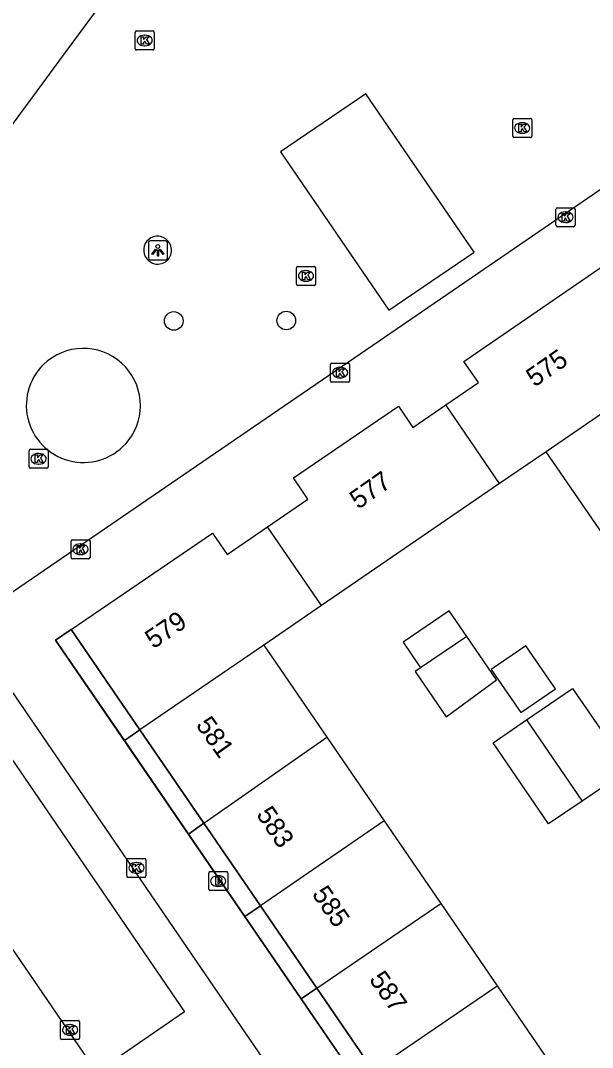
# Model space of a CAD drawing. Extents: x 155275 to 156263, y 382654 to 383635.
# Drawn here: x 155775.3 to 155805.4, y 383214.4 to 383268.4 of the extents above; entities that cross this region are included whole.
import ezdxf

# ---------------------------------------------------------------- set-up
doc = ezdxf.new("R2010")
doc.units = 0
for name, color, linetype in [('IMGEO_Boom', 7, 'Continuous'), ('IMGEO_Brandkraan', 7, 'Continuous'), ('IMGEO_Kolk', 7, 'Continuous'), ('IMGEO_Lichtpunt', 7, 'Continuous'), ('IMGEO_Pand', 7, 'Continuous'), ('IMGEO_Pand_nummerreeks', 7, 'Continuous'), ('IMGEO_Pand_overbouw', 7, 'Continuous'), ('IMGEO_Rijbaan_lokaal_open', 7, 'Continuous'), ('IMGEO_Voetpad_open', 7, 'Continuous')]:
    doc.layers.add(name, color=color, linetype=linetype)

msp = doc.modelspace()

# ---------------------------------------------------------------- linework, layer by layer
at = {"layer": 'IMGEO_Boom'}
for centre in [(155789.292, 383252.661), (155783.378, 383252.641)]:
    msp.add_circle(centre, 0.489, dxfattribs=at)
at = {"layer": 'IMGEO_Brandkraan'}
for p, q in [((155785.216, 383222.754), (155785.216, 383223.606)), ((155785.291, 383223.68), (155786.143, 383223.68)), ((155785.704, 383223.46), (155785.729, 383223.46)), ((155786.217, 383223.606), (155786.217, 383222.754)), ((155785.727, 383222.9), (155785.702, 383222.9)), ((155786.143, 383222.68), (155785.291, 383222.68))]:
    msp.add_line(p, q, dxfattribs=at)
for points in [[(155785.216, 383222.754), (155785.216, 383223.606)], [(155785.291, 383223.68), (155786.143, 383223.68)], [(155786.217, 383223.606), (155786.217, 383222.754)], [(155785.564, 383223.38), (155785.564, 383222.98), (155785.777, 383222.98)], [(155785.795, 383223.38), (155785.564, 383223.38)], [(155785.743, 383223.299), (155785.689, 383223.299), (155785.689, 383223.223)], [(155785.689, 383223.223), (155785.742, 383223.223)], [(155785.751, 383223.147), (155785.689, 383223.147), (155785.689, 383223.066)], [(155785.689, 383223.066), (155785.751, 383223.066)], [(155786.143, 383222.68), (155785.291, 383222.68)]]:
    msp.add_lwpolyline(points, dxfattribs=at)
for centre, radius, start, end in [((155785.293, 383223.604), 0.0765, 91.552, 178.448), ((155785.293, 383223.604), 0.0765, 91.552, 178.448), ((155786.141, 383223.604), 0.0765, 1.552, 88.448), ((155786.141, 383223.604), 0.0765, 1.552, 88.448), ((155785.744, 383223.261), 0.0379, 267.8285, 90.9355), ((155785.752, 383223.106), 0.0404, 269.8759, 90.5077), ((155785.783, 383223.231), 0.251, 268.6676, 293.5347), ((155785.799, 383223.235), 0.145, 59.4692, 91.5367), ((155785.824, 383223.282), 0.0922, 285.5137, 58.1501), ((155785.829, 383223.09), 0.105, 301.3115, 78.989), ((155785.293, 383222.756), 0.0765, 181.552, 268.448), ((155785.293, 383222.756), 0.0765, 181.552, 268.448), ((155786.141, 383222.756), 0.0765, 271.552, 358.448), ((155786.141, 383222.756), 0.0765, 271.552, 358.448)]:
    msp.add_arc(centre, radius, start, end, dxfattribs=at)
for centre, major_axis, ratio, start_param, end_param in [((155785.703, 383223.18), (-0.387, 0.002), 0.722429, 4.712389, 7.853982), ((155785.728, 383223.18), (-0.39, 0.002), 0.717154, 1.570796, 4.712389)]:
    msp.add_ellipse(centre, major_axis=major_axis, ratio=ratio, start_param=start_param, end_param=end_param, dxfattribs=at)
at = {"layer": 'IMGEO_Kolk'}
for p, q in [((155781.349, 383266.964), (155781.349, 383267.816)), ((155781.424, 383267.89), (155782.276, 383267.89)), ((155782.35, 383267.816), (155782.35, 383266.964)), ((155781.837, 383267.67), (155781.862, 383267.67)), ((155782.276, 383266.89), (155781.424, 383266.89)), ((155781.86, 383267.11), (155781.835, 383267.11)), ((155801.197, 383262.362), (155801.197, 383263.214)), ((155801.272, 383263.288), (155802.124, 383263.288)), ((155801.685, 383263.068), (155801.71, 383263.068)), ((155802.198, 383263.214), (155802.198, 383262.362)), ((155801.708, 383262.508), (155801.683, 383262.508)), ((155802.124, 383262.288), (155801.272, 383262.288)), ((155803.546, 383258.596), (155804.398, 383258.596)), ((155803.471, 383257.67), (155803.471, 383258.522)), ((155803.959, 383258.376), (155803.984, 383258.376)), ((155804.472, 383258.522), (155804.472, 383257.67)), ((155804.398, 383257.596), (155803.546, 383257.596)), ((155803.982, 383257.816), (155803.957, 383257.816)), ((155789.828, 383254.582), (155789.828, 383255.434)), ((155789.903, 383255.508), (155790.755, 383255.508)), ((155790.829, 383255.434), (155790.829, 383254.582)), ((155790.316, 383255.288), (155790.341, 383255.288)), ((155790.755, 383254.508), (155789.903, 383254.508)), ((155790.339, 383254.728), (155790.314, 383254.728)), ((155791.619, 383249.496), (155791.619, 383250.348)), ((155791.694, 383250.422), (155792.546, 383250.422)), ((155792.107, 383250.202), (155792.132, 383250.202)), ((155792.62, 383250.348), (155792.62, 383249.496)), ((155792.546, 383249.422), (155791.694, 383249.422)), ((155792.13, 383249.642), (155792.105, 383249.642)), ((155775.773, 383244.964), (155775.773, 383245.816)), ((155775.848, 383245.89), (155776.7, 383245.89)), ((155776.261, 383245.67), (155776.286, 383245.67)), ((155776.774, 383245.816), (155776.774, 383244.964)), ((155776.284, 383245.11), (155776.259, 383245.11)), ((155776.7, 383244.89), (155775.848, 383244.89)), ((155777.978, 383240.206), (155777.978, 383241.058)), ((155778.053, 383241.132), (155778.905, 383241.132)), ((155778.466, 383240.912), (155778.491, 383240.912)), ((155778.979, 383241.058), (155778.979, 383240.206)), ((155778.489, 383240.352), (155778.464, 383240.352)), ((155778.905, 383240.132), (155778.053, 383240.132)), ((155780.913, 383223.451), (155780.913, 383224.303)), ((155780.988, 383224.377), (155781.84, 383224.377)), ((155781.401, 383224.157), (155781.426, 383224.157)), ((155781.914, 383224.303), (155781.914, 383223.451)), ((155781.424, 383223.597), (155781.399, 383223.597)), ((155781.84, 383223.377), (155780.988, 383223.377)), ((155777.425, 383214.927), (155777.425, 383215.779)), ((155777.5, 383215.853), (155778.352, 383215.853)), ((155777.913, 383215.633), (155777.938, 383215.633)), ((155778.426, 383215.779), (155778.426, 383214.927)), ((155778.352, 383214.853), (155777.5, 383214.853)), ((155777.936, 383215.073), (155777.911, 383215.073))]:
    msp.add_line(p, q, dxfattribs=at)
for points in [[(155781.349, 383266.964), (155781.349, 383267.816)], [(155781.424, 383267.89), (155782.276, 383267.89)], [(155782.35, 383267.816), (155782.35, 383266.964)], [(155781.67, 383267.59), (155781.793, 383267.59), (155781.793, 383267.439), (155781.923, 383267.59), (155782.087, 383267.59), (155781.941, 383267.439), (155782.094, 383267.19), (155781.942, 383267.19), (155781.857, 383267.354), (155781.793, 383267.287), (155781.793, 383267.19), (155781.67, 383267.19), (155781.67, 383267.59)], [(155782.276, 383266.89), (155781.424, 383266.89)], [(155801.197, 383262.362), (155801.197, 383263.214)], [(155801.272, 383263.288), (155802.124, 383263.288)], [(155801.518, 383262.988), (155801.641, 383262.988), (155801.641, 383262.837), (155801.771, 383262.988), (155801.935, 383262.988), (155801.789, 383262.837), (155801.942, 383262.588), (155801.79, 383262.588), (155801.705, 383262.752), (155801.641, 383262.685), (155801.641, 383262.588), (155801.518, 383262.588), (155801.518, 383262.988)], [(155802.198, 383263.214), (155802.198, 383262.362)], [(155802.124, 383262.288), (155801.272, 383262.288)], [(155803.546, 383258.596), (155804.398, 383258.596)], [(155803.471, 383257.67), (155803.471, 383258.522)], [(155803.792, 383258.296), (155803.915, 383258.296), (155803.915, 383258.145), (155804.045, 383258.296), (155804.209, 383258.296), (155804.063, 383258.145), (155804.216, 383257.896), (155804.064, 383257.896), (155803.979, 383258.06), (155803.915, 383257.993), (155803.915, 383257.896), (155803.792, 383257.896), (155803.792, 383258.296)], [(155804.472, 383258.522), (155804.472, 383257.67)], [(155804.398, 383257.596), (155803.546, 383257.596)], [(155789.828, 383254.582), (155789.828, 383255.434)], [(155789.903, 383255.508), (155790.755, 383255.508)], [(155790.829, 383255.434), (155790.829, 383254.582)], [(155790.149, 383255.208), (155790.272, 383255.208), (155790.272, 383255.057), (155790.402, 383255.208), (155790.566, 383255.208), (155790.42, 383255.057), (155790.573, 383254.808), (155790.421, 383254.808), (155790.336, 383254.972), (155790.272, 383254.905), (155790.272, 383254.808), (155790.149, 383254.808), (155790.149, 383255.208)], [(155790.755, 383254.508), (155789.903, 383254.508)], [(155791.619, 383249.496), (155791.619, 383250.348)], [(155791.694, 383250.422), (155792.546, 383250.422)], [(155791.94, 383250.122), (155792.063, 383250.122), (155792.063, 383249.971), (155792.193, 383250.122), (155792.357, 383250.122), (155792.211, 383249.971), (155792.364, 383249.722), (155792.212, 383249.722), (155792.127, 383249.886), (155792.063, 383249.819), (155792.063, 383249.722), (155791.94, 383249.722), (155791.94, 383250.122)], [(155792.62, 383250.348), (155792.62, 383249.496)], [(155792.546, 383249.422), (155791.694, 383249.422)], [(155775.773, 383244.964), (155775.773, 383245.816)], [(155775.848, 383245.89), (155776.7, 383245.89)], [(155776.094, 383245.59), (155776.217, 383245.59), (155776.217, 383245.439), (155776.347, 383245.59), (155776.511, 383245.59), (155776.365, 383245.439), (155776.518, 383245.19), (155776.366, 383245.19), (155776.281, 383245.354), (155776.217, 383245.287), (155776.217, 383245.19), (155776.094, 383245.19), (155776.094, 383245.59)], [(155776.774, 383245.816), (155776.774, 383244.964)], [(155776.7, 383244.89), (155775.848, 383244.89)], [(155777.978, 383240.206), (155777.978, 383241.058)], [(155778.053, 383241.132), (155778.905, 383241.132)], [(155778.299, 383240.832), (155778.422, 383240.832), (155778.422, 383240.681), (155778.552, 383240.832), (155778.716, 383240.832), (155778.57, 383240.681), (155778.723, 383240.432), (155778.571, 383240.432), (155778.486, 383240.596), (155778.422, 383240.529), (155778.422, 383240.432), (155778.299, 383240.432), (155778.299, 383240.832)], [(155778.979, 383241.058), (155778.979, 383240.206)], [(155778.905, 383240.132), (155778.053, 383240.132)], [(155780.913, 383223.451), (155780.913, 383224.303)], [(155780.988, 383224.377), (155781.84, 383224.377)], [(155781.234, 383224.077), (155781.357, 383224.077), (155781.357, 383223.926), (155781.487, 383224.077), (155781.651, 383224.077), (155781.505, 383223.926), (155781.658, 383223.677), (155781.506, 383223.677), (155781.421, 383223.841), (155781.357, 383223.774), (155781.357, 383223.677), (155781.234, 383223.677), (155781.234, 383224.077)], [(155781.914, 383224.303), (155781.914, 383223.451)], [(155781.84, 383223.377), (155780.988, 383223.377)], [(155777.425, 383214.927), (155777.425, 383215.779)], [(155777.5, 383215.853), (155778.352, 383215.853)], [(155777.746, 383215.553), (155777.869, 383215.553), (155777.869, 383215.402), (155777.999, 383215.553), (155778.163, 383215.553), (155778.017, 383215.402), (155778.17, 383215.153), (155778.018, 383215.153), (155777.933, 383215.317), (155777.869, 383215.25), (155777.869, 383215.153), (155777.746, 383215.153), (155777.746, 383215.553)], [(155778.426, 383215.779), (155778.426, 383214.927)], [(155778.352, 383214.853), (155777.5, 383214.853)]]:
    msp.add_lwpolyline(points, dxfattribs=at)
for centre, start, end in [((155781.426, 383267.814), 91.552, 178.448), ((155781.426, 383267.814), 91.552, 178.448), ((155782.274, 383267.814), 1.552, 88.448), ((155782.274, 383267.814), 1.552, 88.448), ((155781.426, 383266.966), 181.552, 268.448), ((155781.426, 383266.966), 181.552, 268.448), ((155782.274, 383266.966), 271.552, 358.448), ((155782.274, 383266.966), 271.552, 358.448), ((155801.274, 383263.212), 91.552, 178.448), ((155801.274, 383263.212), 91.552, 178.448), ((155802.122, 383263.212), 1.552, 88.448), ((155802.122, 383263.212), 1.552, 88.448), ((155801.274, 383262.364), 181.552, 268.448), ((155801.274, 383262.364), 181.552, 268.448), ((155802.122, 383262.364), 271.552, 358.448), ((155802.122, 383262.364), 271.552, 358.448), ((155803.548, 383258.52), 91.552, 178.448), ((155803.548, 383258.52), 91.552, 178.448), ((155804.396, 383258.52), 1.552, 88.448), ((155804.396, 383258.52), 1.552, 88.448), ((155803.548, 383257.672), 181.552, 268.448), ((155803.548, 383257.672), 181.552, 268.448), ((155804.396, 383257.672), 271.552, 358.448), ((155804.396, 383257.672), 271.552, 358.448), ((155789.905, 383255.432), 91.552, 178.448), ((155789.905, 383255.432), 91.552, 178.448), ((155790.753, 383255.432), 1.552, 88.448), ((155790.753, 383255.432), 1.552, 88.448), ((155789.905, 383254.584), 181.552, 268.448), ((155789.905, 383254.584), 181.552, 268.448), ((155790.753, 383254.584), 271.552, 358.448), ((155790.753, 383254.584), 271.552, 358.448), ((155791.696, 383250.346), 91.552, 178.448), ((155791.696, 383250.346), 91.552, 178.448), ((155792.544, 383250.346), 1.552, 88.448), ((155792.544, 383250.346), 1.552, 88.448), ((155791.696, 383249.498), 181.552, 268.448), ((155791.696, 383249.498), 181.552, 268.448), ((155792.544, 383249.498), 271.552, 358.448), ((155792.544, 383249.498), 271.552, 358.448), ((155775.85, 383245.814), 91.552, 178.448), ((155775.85, 383245.814), 91.552, 178.448), ((155776.698, 383245.814), 1.552, 88.448), ((155776.698, 383245.814), 1.552, 88.448), ((155775.85, 383244.966), 181.552, 268.448), ((155775.85, 383244.966), 181.552, 268.448), ((155776.698, 383244.966), 271.552, 358.448), ((155776.698, 383244.966), 271.552, 358.448), ((155778.055, 383241.056), 91.552, 178.448), ((155778.055, 383241.056), 91.552, 178.448), ((155778.903, 383241.056), 1.552, 88.448), ((155778.903, 383241.056), 1.552, 88.448), ((155778.055, 383240.208), 181.552, 268.448), ((155778.055, 383240.208), 181.552, 268.448), ((155778.903, 383240.208), 271.552, 358.448), ((155778.903, 383240.208), 271.552, 358.448), ((155780.99, 383224.301), 91.552, 178.448), ((155780.99, 383224.301), 91.552, 178.448), ((155781.838, 383224.301), 1.552, 88.448), ((155781.838, 383224.301), 1.552, 88.448), ((155780.99, 383223.453), 181.552, 268.448), ((155780.99, 383223.453), 181.552, 268.448), ((155781.838, 383223.453), 271.552, 358.448), ((155781.838, 383223.453), 271.552, 358.448), ((155777.502, 383215.777), 91.552, 178.448), ((155777.502, 383215.777), 91.552, 178.448), ((155778.35, 383215.777), 1.552, 88.448), ((155778.35, 383215.777), 1.552, 88.448), ((155777.502, 383214.929), 181.552, 268.448), ((155777.502, 383214.929), 181.552, 268.448), ((155778.35, 383214.929), 271.552, 358.448), ((155778.35, 383214.929), 271.552, 358.448)]:
    msp.add_arc(centre, 0.0765, start, end, dxfattribs=at)
for centre, major_axis, ratio, start_param, end_param in [((155781.836, 383267.39), (-0.387, 0.002), 0.722429, 4.712389, 7.853982), ((155781.861, 383267.39), (-0.39, 0.002), 0.717154, 1.570796, 4.712389), ((155801.684, 383262.788), (-0.387, 0.002), 0.722429, 4.712389, 7.853982), ((155801.709, 383262.788), (-0.39, 0.002), 0.717154, 1.570796, 4.712389), ((155803.958, 383258.096), (-0.387, 0.002), 0.722429, 4.712389, 7.853982), ((155803.983, 383258.096), (-0.39, 0.002), 0.717154, 1.570796, 4.712389), ((155790.315, 383255.008), (-0.387, 0.002), 0.722429, 4.712389, 7.853982), ((155790.34, 383255.008), (-0.39, 0.002), 0.717154, 1.570796, 4.712389), ((155792.106, 383249.922), (-0.387, 0.002), 0.722429, 4.712389, 7.853982), ((155792.131, 383249.922), (-0.39, 0.002), 0.717154, 1.570796, 4.712389), ((155776.26, 383245.39), (-0.387, 0.002), 0.722429, 4.712389, 7.853982), ((155776.285, 383245.39), (-0.39, 0.002), 0.717154, 1.570796, 4.712389), ((155778.465, 383240.632), (-0.387, 0.002), 0.722429, 4.712389, 7.853982), ((155778.49, 383240.632), (-0.39, 0.002), 0.717154, 1.570796, 4.712389), ((155781.4, 383223.877), (-0.387, 0.002), 0.722429, 4.712389, 7.853982), ((155781.425, 383223.877), (-0.39, 0.002), 0.717154, 1.570796, 4.712389), ((155777.912, 383215.353), (-0.387, 0.002), 0.722429, 4.712389, 7.853982), ((155777.937, 383215.353), (-0.39, 0.002), 0.717154, 1.570796, 4.712389)]:
    msp.add_ellipse(centre, major_axis=major_axis, ratio=ratio, start_param=start_param, end_param=end_param, dxfattribs=at)
at = {"layer": 'IMGEO_Lichtpunt'}
for p, q in [((155782.044, 383256.758), (155782.044, 383255.951)), ((155782.044, 383256.758), (155782.044, 383255.951)), ((155782.946, 383256.853), (155782.138, 383256.853)), ((155782.946, 383256.853), (155782.138, 383256.853)), ((155783.04, 383255.951), (155783.04, 383256.758)), ((155783.04, 383255.951), (155783.04, 383256.758)), ((155782.138, 383255.857), (155782.946, 383255.857)), ((155782.138, 383255.857), (155782.946, 383255.857))]:
    msp.add_line(p, q, dxfattribs=at)
for points in [[(155782.418, 383256.422), (155782.457, 383256.394), (155782.269, 383256.132), (155782.231, 383256.159), (155782.418, 383256.422)], [(155782.52, 383256.374), (155782.567, 383256.374), (155782.567, 383256.052), (155782.52, 383256.052), (155782.52, 383256.374)], [(155782.63, 383256.394), (155782.668, 383256.421), (155782.855, 383256.159), (155782.816, 383256.131), (155782.63, 383256.394)]]:
    msp.add_lwpolyline(points, dxfattribs=at)
msp.add_circle((155782.543, 383256.556), 0.0994, dxfattribs=at)
for centre, start, end in [((155782.138, 383256.758), 90, 180), ((155782.138, 383256.758), 90, 180), ((155782.946, 383256.758), 0, 90), ((155782.946, 383256.758), 0, 90), ((155782.138, 383255.951), 180, 270), ((155782.138, 383255.951), 180, 270), ((155782.946, 383255.951), 270, 0), ((155782.946, 383255.951), 270, 360)]:
    msp.add_arc(centre, 0.0946, start, end, dxfattribs=at)
at = {"layer": 'IMGEO_Pand'}
for points in [[(155797.672, 383248.223), (155799.39, 383249.402), (155798.628, 383250.516), (155806.057, 383255.604)], [(155809.653, 383250.348), (155802.96, 383245.762)], [(155788.309, 383241.815), (155790.427, 383243.266), (155789.665, 383244.381), (155795.193, 383248.159), (155795.954, 383247.044), (155797.672, 383248.223)], [(155800.509, 383244.083), (155797.672, 383248.223)], [(155802.96, 383245.762), (155800.509, 383244.083)], [(155805.927, 383241.431), (155802.96, 383245.762)], [(155800.509, 383244.083), (155791.148, 383237.67)], [(155777.993, 383236.404), (155785.416, 383241.471), (155786.19, 383240.364), (155788.309, 383241.815)], [(155791.148, 383237.67), (155788.309, 383241.815)], [(155791.148, 383237.67), (155788.11, 383235.589)], [(155798.777, 383236.052), (155797.861, 383237.388), (155795.433, 383235.745), (155796.352, 383234.391)], [(155777.993, 383236.404), (155781.602, 383231.129)], [(155796.352, 383234.391), (155796.074, 383234.2), (155797.7, 383231.828), (155800.349, 383233.758), (155798.777, 383236.052)], [(155798.777, 383236.052), (155796.352, 383234.391)], [(155788.11, 383235.589), (155781.602, 383231.129)], [(155788.11, 383235.589), (155791.428, 383230.746)], [(155801.883, 383235.554), (155800.071, 383234.313), (155801.627, 383232.043), (155803.439, 383233.284), (155801.883, 383235.554)], [(155801.919, 383231.657), (155804.339, 383233.315), (155807.28, 383229.024), (155804.848, 383227.383)], [(155804.848, 383227.383), (155803.081, 383226.191), (155800.161, 383230.452), (155801.919, 383231.657)], [(155801.919, 383231.657), (155804.848, 383227.383)], [(155781.602, 383231.129), (155784.96, 383226.22)], [(155784.96, 383226.22), (155791.428, 383230.746)], [(155791.428, 383230.746), (155794.446, 383226.342)], [(155784.96, 383226.22), (155787.93, 383221.878)], [(155794.446, 383226.342), (155787.93, 383221.878)], [(155794.446, 383226.342), (155797.413, 383222.011)], [(155787.93, 383221.878), (155790.894, 383217.545)], [(155790.894, 383217.545), (155797.413, 383222.011)], [(155797.413, 383222.011), (155800.38, 383217.68)], [(155790.894, 383217.545), (155793.858, 383213.211)], [(155793.858, 383213.211), (155800.38, 383217.68)], [(155800.38, 383217.68), (155803.347, 383213.349)]]:
    msp.add_lwpolyline(points, dxfattribs=at)
at = {"layer": 'IMGEO_Pand_overbouw'}
for points in [[(155781.602, 383231.129), (155777.993, 383236.404), (155777.166, 383235.849), (155780.781, 383230.567)], [(155784.96, 383226.22), (155781.602, 383231.129), (155780.781, 383230.567), (155784.146, 383225.65)], [(155784.96, 383226.22), (155784.146, 383225.65), (155787.112, 383221.317), (155787.93, 383221.878)], [(155787.93, 383221.878), (155787.112, 383221.317), (155790.077, 383216.985), (155790.894, 383217.545)], [(155793.858, 383213.211), (155790.894, 383217.545), (155790.077, 383216.985), (155793.042, 383212.652)]]:
    msp.add_lwpolyline(points, close=True, dxfattribs=at)
at = {"layer": 'IMGEO_Rijbaan_lokaal_open'}
for points in [[(155817.087, 383320.059), (155811.131, 383312.082), (155798.256, 383294.644), (155789.533, 383282.828), (155777.762, 383266.885), (155770.477, 383257.018), (155750.942, 383230.559), (155753.136, 383227.355), (155767.095, 383206.967), (155771.224, 383200.936), (155773.915, 383197.049), (155790.895, 383199.943), (155792.328, 383200.159), (155792.43, 383196.787)], [(155788.989, 383261.531), (155794.675, 383253.201), (155799.161, 383256.263), (155793.475, 383264.593), (155788.989, 383261.531)], [(155843.488, 383208.615), (155827.482, 383232.012), (155821.26, 383241.107), (155811.353, 383255.588), (155807.738, 383260.872), (155793.514, 383251.129), (155783.237, 383244.091), (155772.43, 383236.689), (155786.907, 383215.526), (155798.734, 383198.236)], [(155783.949, 383216.297), (155779.333, 383213.139), (155768.037, 383229.651), (155772.653, 383232.81), (155783.949, 383216.297)]]:
    msp.add_lwpolyline(points, dxfattribs=at)
for centre, radius, start, end in [((155782.521, 383256.373), 0.725, 39.6791, 219.4562), ((155782.537, 383256.355), 0.725, 217.5291, 41.6061), ((155778.62, 383248.191), 3.005, 321.9696, 134.2221), ((155778.63, 383248.203), 3.004, 134.5179, 321.6738)]:
    msp.add_arc(centre, radius, start, end, dxfattribs=at)
at = {"layer": 'IMGEO_Voetpad_open'}
msp.add_lwpolyline([(155802.561, 383198.744), (155777.166, 383235.849), (155777.993, 383236.404)], dxfattribs=at)

# ---------------------------------------------------------------- texts
at = {"layer": 'IMGEO_Pand_nummerreeks'}
for s, rotation, p in [('575', 34.796, (155802.348, 383249.13)), ('577', 35.0893, (155793.076, 383242.703)), ('579', 34.1932, (155782.309, 383235.365)), ('581', 305.4596, (155784.504, 383231.386)), ('583', 303.9965, (155787.686, 383226.684)), ('585', 304.4482, (155790.609, 383222.497)), ('587', 304.9607, (155793.615, 383218.007))]:
    msp.add_text(s, height=1, rotation=rotation, dxfattribs=at).set_placement(p)

doc.saveas('drawing.dxf')
